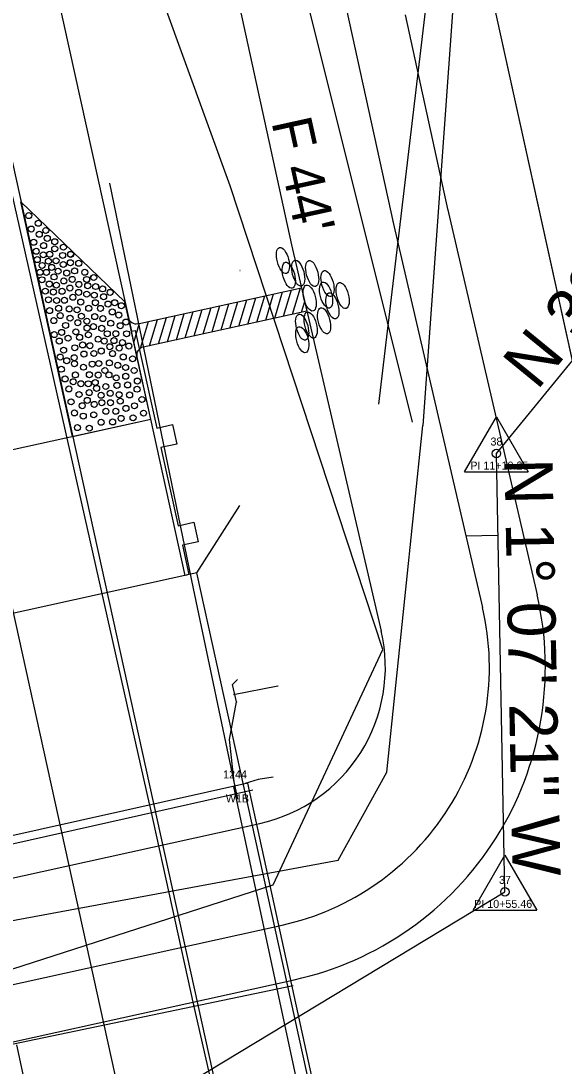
# Model space of a CAD drawing. Extents: x 2519952 to 2531965, y 848341 to 887632.
# Drawn here: x 2528431.4 to 2528499.3, y 851960.5 to 852091.1 of the extents above; entities that cross this region are included whole.
import ezdxf

# ---------------------------------------------------------------- set-up
doc = ezdxf.new("R2010")
doc.units = 0
for name, color, linetype in [('RD_EV_JW', 7, 'Continuous'), ('RD_EX_BldgApp', 7, 'Continuous'), ('RD_EX_BldgApp_txCode', 7, 'Continuous'), ('RD_EX_Bridge', 7, 'Continuous'), ('RD_EX_Conc', 7, 'Continuous'), ('RD_EX_DR_Pipe', 7, 'Continuous'), ('RD_EX_DV_Prop', 7, 'Continuous'), ('RD_EX_GuardRail', 7, 'Continuous'), ('RD_EX_H2O', 7, 'Continuous'), ('RD_EX_Misc', 7, 'Continuous'), ('RD_EX_Road', 7, 'Continuous'), ('RD_EX_RW', 7, 'Continuous'), ('RD_EX_VEG', 7, 'Continuous'), ('RD_HC_Cl', 7, 'Continuous'), ('RD_HC_Data', 7, 'Continuous'), ('RD_HC_Data_Tic', 7, 'Continuous'), ('RD_HC_txCode', 7, 'Continuous'), ('RD_PD_BCA', 7, 'Continuous'), ('RD_PD_Bridge', 7, 'Continuous'), ('RD_PD_CstnLmt', 7, 'Continuous'), ('RD_PD_DR_ErosCtrl', 7, 'Continuous'), ('RD_PD_Final_TrvlWay', 7, 'Continuous'), ('RD_PD_GR', 7, 'Continuous'), ('RD_PD_PaveShd', 7, 'Continuous'), ('RD_PD_TX_CstnLmt', 7, 'Continuous'), ('RD_SMD_Locator', 7, 'Continuous')]:
    doc.layers.add(name, color=color, linetype=linetype)

# ---------------------------------------------------------------- blocks, each defined once
blk = doc.blocks.new('TBC1')
at = {"layer": 'RD_PD_GR'}
blk.add_lwpolyline([(12.5, 2.5), (15, 2.5), (15, 0.49), (25, 0.49), (25, 2.5), (27.5, 2.5), (27.5, 0.49), (31.25, 0.49), (31.25, 0), (0, 0), (0, 0.49), (12.5, 0.49)], close=True, dxfattribs=at)

msp = doc.modelspace()

# ---------------------------------------------------------------- linework, layer by layer
at = {"layer": 'RD_EV_JW'}
msp.add_lwpolyline([(2528415.9, 851967.97), (2528462.94, 851983.14), (2528476.65, 852012.57), (2528457.58, 852070.48), (2528432.54, 852139.5), (2528402.93, 852278.26), (2528385.41, 852350.81), (2528363.37, 852451.24), (2528353.45, 852495.96), (2528382.56, 852499.75), (2528412.03, 852505.69)], dxfattribs=at)
at = {"layer": 'RD_EX_BldgApp'}
msp.add_lwpolyline([(2528474.17, 851921.38), (2528466.05, 851957.9), (2528458.04, 851995.44)], dxfattribs=at)
at = {"layer": 'RD_EX_Bridge'}
for points in [[(2528462.93, 851996.59), (2528461.07, 851996.29), (2528459.44, 851995.8)], [(2528429.64, 851911.53), (2528475.93, 851921.77), (2528459.8, 851995.83), (2528412.88, 851985.37), (2528429.64, 851911.53)]]:
    msp.add_lwpolyline(points, dxfattribs=at)
at = {"layer": 'RD_EX_Conc'}
msp.add_lwpolyline([(2528458.07, 851996.01), (2528457.47, 852001.29), (2528458.38, 852005.99), (2528457.85, 852008.18), (2528458.5, 852008.82)], dxfattribs=at)
at = {"layer": 'RD_EX_DR_Pipe'}
msp.add_line((2528458, 852006.91), (2528463.54, 852007.99), dxfattribs=at)
at = {"layer": 'RD_EX_DV_Prop'}
msp.add_line((2528484.88, 852118.66), (2528549.4, 851825.68), dxfattribs=at)
at = {"layer": 'RD_EX_GuardRail'}
msp.add_lwpolyline([(2528458.52, 851993.85), (2528452.97, 852020.19), (2528442.53, 852070.83)], dxfattribs=at)
at = {"layer": 'RD_EX_H2O'}
for points in [[(2528719.59, 851999.09), (2528691.1, 852047.72), (2528711.96, 852086.66), (2528686.69, 852125.57), (2528637.99, 852160.23), (2528595.34, 852145.76), (2528559.57, 852138.95), (2528529.72, 852106.03), (2528505.05, 852114.18), (2528485.4, 852092.73), (2528481.66, 852040.55)], [(2528393.64, 851981.43), (2528398.43, 851972.78), (2528471.09, 851986.23), (2528477.16, 851997.23), (2528481.66, 852040.55)]]:
    msp.add_lwpolyline(points, dxfattribs=at)
at = {"layer": 'RD_EX_Misc'}
for p, q in [((2528413.19, 851984.4), (2528460.39, 851995)), ((2528465.45, 851970.51), (2528418.56, 851960.74))]:
    msp.add_line(p, q, dxfattribs=at)
msp.add_lwpolyline([(2528721.04, 851999.29), (2528692.03, 852048.08), (2528712.68, 852087), (2528694.26, 852117.1), (2528687.66, 852126.5), (2528638.26, 852161.91), (2528594.97, 852147.21), (2528558.87, 852140.18), (2528529.59, 852106.6), (2528504.69, 852116.44), (2528482.38, 852095.87), (2528476.12, 852043.21)], dxfattribs=at)
at = {"layer": 'RD_EX_Road'}
for p, q in [((2528447.51, 851993.25), (2528425.97, 852088.72)), ((2528447.63, 851992.76), (2528447.51, 851993.25)), ((2528453.04, 851968.08), (2528447.63, 851992.76)), ((2528458.52, 851943.88), (2528453.04, 851968.08)), ((2528436.25, 851938.7), (2528430.91, 851963.15))]:
    msp.add_line(p, q, dxfattribs=at)
at = {"layer": 'RD_EX_RW'}
msp.add_line((2528484.89, 852118.66), (2528549.4, 851825.67), dxfattribs=at)
at = {"layer": 'RD_EX_VEG'}
msp.add_lwpolyline([(2528480.36, 852040.95), (2528466.6, 852096.04), (2528387.76, 852488.16), (2528341.84, 852710.17)], dxfattribs=at)
at = {"layer": 'RD_HC_Cl'}
for p, q in [((2528295.9, 852628.14), (2528852.49, 850100.49)), ((2528490.84, 852037.04), (2528538.4, 852095.17)), ((2528491.91, 851982.26), (2528490.84, 852037.04)), ((2528326.78, 851882.57), (2528491.91, 851982.26))]:
    msp.add_line(p, q, dxfattribs=at)
at = {"layer": 'RD_HC_Data'}
for p, q in [((2528486.87, 852034.74), (2528490.84, 852041.62)), ((2528490.84, 852041.62), (2528494.81, 852034.74)), ((2528486.87, 852034.74), (2528494.81, 852034.74)), ((2528487.94, 851979.97), (2528491.91, 851986.85)), ((2528491.91, 851986.85), (2528495.88, 851979.97)), ((2528487.94, 851979.97), (2528495.88, 851979.97))]:
    msp.add_line(p, q, dxfattribs=at)
for centre in [(2528490.84, 852037.04), (2528491.91, 851982.26)]:
    msp.add_circle(centre, 0.529, dxfattribs=at)
at = {"layer": 'RD_HC_Data_Tic'}
msp.add_line((2528491.04, 852026.78), (2528487.04, 852026.7), dxfattribs=at)
at = {"layer": 'RD_PD_BCA'}
for p, q in [((2528479.43, 852091.86), (2528484.78, 852067.41)), ((2528484.73, 852067.66), (2528495.93, 852019.39))]:
    msp.add_line(p, q, dxfattribs=at)
msp.add_lwpolyline([(2528416.79, 851960.53), (2528465.57, 851971.27)], dxfattribs=at)
msp.add_arc((2528456.97, 852010.34), 40, 282.4185, 13.0724, dxfattribs=at)
at = {"layer": 'RD_PD_Bridge'}
for p, q in [((2528404.67, 852031.88), (2528447.64, 852041.34)), ((2528451.94, 852021.81), (2528447.64, 852041.34)), ((2528453.41, 852022.13), (2528458.79, 852030.56))]:
    msp.add_line(p, q, dxfattribs=at)
for points in [[(2528453.41, 852022.13), (2528407.51, 852012.02)], [(2528481.36, 851895.17), (2528453.41, 852022.13)]]:
    msp.add_lwpolyline(points, dxfattribs=at)
at = {"layer": 'RD_PD_CstnLmt'}
for p, q in [((2528443.88, 852160.82), (2528465.24, 852063.13)), ((2528465.24, 852063.13), (2528476.45, 852014.86))]:
    msp.add_line(p, q, dxfattribs=at)
msp.add_lwpolyline([(2528412.49, 851980.06), (2528461.27, 851990.81)], dxfattribs=at)
msp.add_arc((2528456.97, 852010.34), 20, 282.4185, 13.0724, dxfattribs=at)
at = {"layer": 'RD_PD_DR_ErosCtrl'}
for p, q in [((2528456.58, 852163.6), (2528477.94, 852065.91)), ((2528477.91, 852066.07), (2528489.12, 852017.8))]:
    msp.add_line(p, q, dxfattribs=at)
msp.add_lwpolyline([(2528415.28, 851967.37), (2528464.07, 851978.11)], dxfattribs=at)
msp.add_arc((2528456.97, 852010.34), 33, 282.4185, 13.0724, dxfattribs=at)
at = {"layer": 'RD_PD_Final_TrvlWay'}
msp.add_line((2528396.48, 852227.18), (2528670.67, 850982.01), dxfattribs=at)
at = {"layer": 'RD_PD_GR'}
msp.add_line((2528396.83, 852272.06), (2528445.22, 852052.33), dxfattribs=at)
at = {"layer": 'RD_PD_PaveShd'}
for p, q in [((2528431.42, 852068.49), (2528444.41, 852055.99)), ((2528437.87, 852039.19), (2528431.42, 852068.49)), ((2528446.04, 852053.27), (2528466.49, 852057.77)), ((2528459.79, 852053.22), (2528460.77, 852056.51)), ((2528459.79, 852053.22), (2528460.77, 852056.51)), ((2528460.9, 852053.47), (2528461.89, 852056.75)), ((2528462.02, 852053.71), (2528463, 852057)), ((2528462.02, 852053.71), (2528463, 852057)), ((2528463.14, 852053.96), (2528464.12, 852057.25)), ((2528463.14, 852053.96), (2528464.12, 852057.25)), ((2528464.25, 852054.2), (2528465.24, 852057.49)), ((2528464.25, 852054.2), (2528465.12, 852057.09)), ((2528465.37, 852054.45), (2528466.36, 852057.74)), ((2528465.37, 852054.45), (2528466.36, 852057.74)), ((2528466.49, 852057.77), (2528467.17, 852054.84)), ((2528445.06, 852053.06), (2528444.41, 852055.99)), ((2528454.2, 852051.99), (2528455.18, 852055.28)), ((2528454.2, 852051.99), (2528455.18, 852055.28)), ((2528455.32, 852052.24), (2528456.3, 852055.53)), ((2528455.32, 852052.24), (2528456.3, 852055.53)), ((2528456.43, 852052.49), (2528457.42, 852055.77)), ((2528456.43, 852052.49), (2528457.42, 852055.77)), ((2528457.55, 852052.73), (2528458.54, 852056.02)), ((2528457.55, 852052.73), (2528458.54, 852056.02)), ((2528458.67, 852052.98), (2528459.65, 852056.26)), ((2528458.67, 852052.98), (2528459.65, 852056.26)), ((2528460.9, 852053.47), (2528461.77, 852056.35)), ((2528466.49, 852054.69), (2528466.89, 852056.04)), ((2528466.49, 852054.69), (2528466.89, 852056.04)), ((2528467.17, 852054.84), (2528446.68, 852050.34)), ((2528448.61, 852050.77), (2528449.6, 852054.05)), ((2528448.61, 852050.77), (2528449.6, 852054.05)), ((2528449.73, 852051.01), (2528450.71, 852054.3)), ((2528449.73, 852051.01), (2528450.71, 852054.3)), ((2528450.85, 852051.26), (2528451.83, 852054.55)), ((2528451.96, 852051.5), (2528452.95, 852054.79)), ((2528451.96, 852051.5), (2528452.95, 852054.79)), ((2528453.08, 852051.75), (2528454.07, 852055.04)), ((2528453.08, 852051.75), (2528454.07, 852055.04)), ((2528445.71, 852050.13), (2528445.06, 852053.06)), ((2528445.53, 852050.93), (2528446.24, 852053.32)), ((2528446.36, 852050.21), (2528447.36, 852053.56)), ((2528447.5, 852050.52), (2528448.48, 852053.81)), ((2528447.5, 852050.52), (2528448.48, 852053.81)), ((2528447.64, 852041.34), (2528445.71, 852050.13)), ((2528437.87, 852039.19), (2528447.64, 852041.34))]:
    msp.add_line(p, q, dxfattribs=at)
for centre in [(2528432.4, 852066.78), (2528433.59, 852065.82), (2528433.59, 852065.82), (2528432.7, 852065.1), (2528432.7, 852065.1), (2528433.71, 852064.45), (2528433.71, 852064.45), (2528434.53, 852064.92), (2528434.53, 852064.92), (2528433.02, 852063.44), (2528433.02, 852063.44), (2528434.26, 852063.03), (2528434.26, 852063.03), (2528434.71, 852063.93), (2528434.71, 852063.93), (2528435.64, 852063.51), (2528436.73, 852062.83), (2528436.73, 852062.83), (2528433.33, 852062.32), (2528433.33, 852062.32), (2528434.21, 852061.88), (2528434.21, 852061.88), (2528435.02, 852061.95), (2528435.02, 852061.95), (2528435.64, 852062.63), (2528435.64, 852062.63), (2528436.63, 852061.8), (2528436.63, 852061.8), (2528437.61, 852061.96), (2528437.64, 852061.93), (2528433.47, 852061.28), (2528433.47, 852061.28), (2528434.07, 852060.55), (2528434.07, 852060.55), (2528434.85, 852061.08), (2528434.85, 852061.08), (2528435.27, 852060.31), (2528435.27, 852060.31), (2528435.81, 852061.13), (2528435.81, 852061.13), (2528436.71, 852060.67), (2528436.71, 852060.67), (2528437.6, 852060.89), (2528437.6, 852060.89), (2528438.64, 852060.82), (2528438.64, 852060.82), (2528433.81, 852059.7), (2528433.81, 852059.7), (2528434.05, 852058.76), (2528434.05, 852058.76), (2528434.61, 852059.68), (2528434.61, 852059.68), (2528435.56, 852059.12), (2528435.56, 852059.12), (2528436.07, 852059.83), (2528436.07, 852059.83), (2528437.14, 852059.6), (2528437.14, 852059.6), (2528437.83, 852058.81), (2528437.83, 852058.81), (2528438.13, 852059.87), (2528438.13, 852059.87), (2528439.4, 852059.7), (2528439.4, 852059.7), (2528439.63, 852058.8), (2528439.63, 852058.8), (2528440.52, 852059.04), (2528440.53, 852059.04), (2528434.97, 852058.23), (2528434.97, 852058.23), (2528435.85, 852058.09), (2528435.85, 852058.09), (2528436.78, 852058.61), (2528436.78, 852058.61), (2528437.54, 852057.73), (2528437.54, 852057.73), (2528438.66, 852058.18), (2528438.66, 852058.18), (2528439.77, 852058.02), (2528439.77, 852058.02), (2528440.75, 852057.91), (2528440.75, 852057.91), (2528441.63, 852057.62), (2528441.63, 852057.62), (2528434.46, 852057.34), (2528434.46, 852057.34), (2528434.86, 852056.26), (2528434.86, 852056.26), (2528435.48, 852057.23), (2528435.48, 852057.23), (2528435.88, 852056.17), (2528435.88, 852056.17), (2528436.56, 852057.32), (2528436.56, 852057.32), (2528436.86, 852056.19), (2528436.86, 852056.19), (2528437.91, 852056.57), (2528437.91, 852056.57), (2528438.63, 852057.18), (2528438.63, 852057.18), (2528439.64, 852056.96), (2528439.64, 852056.96), (2528440.59, 852056.84), (2528440.59, 852056.84), (2528441.75, 852056.64), (2528441.75, 852056.64), (2528442.57, 852057.18), (2528442.57, 852057.18), (2528435.01, 852054.91), (2528435.01, 852054.91), (2528436.13, 852055.2), (2528436.13, 852055.2), (2528437.45, 852055.11), (2528437.45, 852055.11), (2528438.43, 852055), (2528438.43, 852055), (2528438.89, 852055.98), (2528438.89, 852055.98), (2528439.89, 852055.19), (2528439.89, 852055.19), (2528440.72, 852055.89), (2528440.72, 852055.89), (2528441.36, 852055.18), (2528441.36, 852055.18), (2528442.31, 852055.73), (2528442.31, 852055.73), (2528443.14, 852055.89), (2528443.14, 852055.89), (2528443.98, 852055.52), (2528443.98, 852055.52), (2528443.98, 852055.52), (2528435.53, 852053.66), (2528435.53, 852053.66), (2528436.33, 852054.28), (2528436.33, 852054.28), (2528437.56, 852053.96), (2528437.56, 852053.96), (2528438.98, 852054.21), (2528438.98, 852054.21), (2528439.66, 852053.59), (2528439.66, 852053.59), (2528440.64, 852054.16), (2528440.64, 852054.16), (2528441.66, 852053.91), (2528441.66, 852053.91), (2528442.84, 852054.74), (2528442.84, 852054.74), (2528443.65, 852054.35), (2528443.65, 852054.35), (2528436.51, 852052.19), (2528436.51, 852052.19), (2528437, 852053.05), (2528437, 852053.05), (2528438.29, 852052.25), (2528438.29, 852052.25), (2528438.53, 852053.39), (2528438.53, 852053.39), (2528439.69, 852052.72), (2528439.69, 852052.72), (2528440.49, 852052.9), (2528440.49, 852052.9), (2528441.52, 852052.69), (2528441.52, 852052.69), (2528442.64, 852053.33), (2528442.64, 852053.33), (2528443.83, 852053.02), (2528443.83, 852053.02), (2528444.55, 852053.48), (2528444.55, 852053.48), (2528435.58, 852051.91), (2528435.58, 852051.91), (2528436.21, 852051.1), (2528436.21, 852051.1), (2528437.31, 852051.46), (2528437.31, 852051.46), (2528438.75, 852051.57), (2528438.75, 852051.57), (2528439.85, 852051.88), (2528439.85, 852051.88), (2528441.07, 852051.33), (2528441.07, 852051.33), (2528441.83, 852051.1), (2528441.83, 852051.1), (2528442.21, 852052.01), (2528442.21, 852052.01), (2528443.05, 852051.15), (2528443.05, 852051.15), (2528443.28, 852052.02), (2528443.28, 852052.02), (2528444.11, 852050.9), (2528444.11, 852050.9), (2528444.63, 852052.01), (2528444.63, 852052.01), (2528436.75, 852049.96), (2528436.75, 852049.96), (2528438.15, 852050.26), (2528438.15, 852050.26), (2528439.13, 852050.61), (2528439.13, 852050.61), (2528440.04, 852050.52), (2528440.04, 852050.52), (2528441.46, 852049.85), (2528441.46, 852049.85), (2528442.53, 852050.39), (2528442.53, 852050.39), (2528443.7, 852050.23), (2528443.7, 852050.23), (2528444.91, 852050.47), (2528444.91, 852050.47), (2528436.33, 852049.1), (2528437.14, 852048.64), (2528437.14, 852048.64), (2528438.08, 852049.02), (2528438.08, 852049.02), (2528438.11, 852048.27), (2528438.11, 852048.27), (2528439.3, 852049.48), (2528439.3, 852049.48), (2528440.54, 852049.55), (2528440.54, 852049.55), (2528441.15, 852048.29), (2528441.15, 852048.29), (2528442.48, 852048.37), (2528442.48, 852048.37), (2528442.87, 852049.53), (2528442.87, 852049.53), (2528444.21, 852049.11), (2528444.21, 852049.11), (2528445.38, 852048.88), (2528445.38, 852048.88), (2528436.47, 852047.58), (2528436.47, 852047.58), (2528439.24, 852047.83), (2528439.24, 852047.83), (2528440.33, 852048.22), (2528440.33, 852048.22), (2528441.91, 852047.42), (2528441.91, 852047.42), (2528443.53, 852048.07), (2528443.53, 852048.07), (2528444.5, 852047.8), (2528444.5, 852047.8), (2528445.57, 852047.42), (2528445.57, 852047.42), (2528436.94, 852046.36), (2528436.94, 852046.36), (2528437.95, 852046.02), (2528437.95, 852046.02), (2528438.23, 852046.87), (2528438.23, 852046.87), (2528438.91, 852045.77), (2528438.91, 852045.77), (2528439.84, 852045.76), (2528439.84, 852045.76), (2528439.97, 852046.89), (2528439.97, 852046.89), (2528440.71, 852045.92), (2528440.71, 852045.92), (2528441.08, 852046.85), (2528441.08, 852046.85), (2528442.42, 852046.87), (2528442.42, 852046.87), (2528443.33, 852046.5), (2528443.33, 852046.5), (2528444.52, 852046.7), (2528444.52, 852046.7), (2528445.98, 852046.1), (2528445.98, 852046.1), (2528437.41, 852045.11), (2528437.41, 852045.11), (2528438.68, 852044.42), (2528438.68, 852044.42), (2528439.95, 852044.66), (2528439.95, 852044.66), (2528440.88, 852045.18), (2528442.03, 852045.42), (2528442.03, 852045.42), (2528442.58, 852044.57), (2528442.58, 852044.57), (2528443.42, 852045.56), (2528443.42, 852045.56), (2528443.69, 852044.39), (2528443.69, 852044.39), (2528444.76, 852045.62), (2528444.76, 852045.62), (2528445.01, 852044.37), (2528445.01, 852044.37), (2528445.93, 852045.08), (2528445.93, 852045.08), (2528437.68, 852043.5), (2528437.68, 852043.5), (2528439.71, 852043.69), (2528439.71, 852043.69), (2528440.58, 852043.19), (2528440.58, 852043.19), (2528441.44, 852044.32), (2528441.44, 852044.32), (2528441.53, 852043.39), (2528441.53, 852043.39), (2528442.61, 852043.39), (2528442.61, 852043.39), (2528443.84, 852043.59), (2528443.84, 852043.59), (2528446.55, 852043.8), (2528446.55, 852043.8), (2528438.11, 852042.11), (2528438.11, 852042.11), (2528439.08, 852043.02), (2528439.08, 852043.02), (2528440.52, 852041.88), (2528440.52, 852041.88), (2528442.04, 852042.32), (2528442.04, 852042.32), (2528443.28, 852042.32), (2528443.28, 852042.32), (2528444.55, 852042.68), (2528444.55, 852042.68), (2528445.61, 852043.01), (2528445.61, 852043.01), (2528446.74, 852042.09), (2528446.74, 852042.09), (2528446.74, 852042.09), (2528439.21, 852041.72), (2528439.21, 852041.72), (2528441.44, 852040.95), (2528441.44, 852040.95), (2528442.88, 852040.99), (2528442.88, 852040.99), (2528443.94, 852041.44), (2528443.94, 852041.44), (2528445.43, 852041.51), (2528445.43, 852041.51), (2528438.49, 852040.28), (2528438.49, 852040.28), (2528439.96, 852040.21), (2528439.96, 852040.21)]:
    msp.add_circle(centre, 0.375, dxfattribs=at)
for centre, start, end in [((2528445.82, 852054.25), 192.4185, 282.3889), ((2528446.9, 852049.37), 102.3889, 192.4185)]:
    msp.add_arc(centre, 1, start, end, dxfattribs=at)
for centre in [(2528464.17, 852061.17), (2528464.9, 852059.32), (2528466.07, 852059.59), (2528466.07, 852059.59), (2528467.82, 852059.54), (2528467.82, 852059.54), (2528469.74, 852058.28), (2528469.74, 852058.28), (2528467.51, 852056.48), (2528467.51, 852056.48), (2528469.56, 852056.85), (2528469.56, 852056.85), (2528471.63, 852056.79), (2528471.63, 852056.79), (2528470.35, 852055.5), (2528470.35, 852055.5), (2528469.31, 852053.63), (2528469.31, 852053.63), (2528466.57, 852052.84), (2528466.57, 852052.84), (2528467.63, 852053.1), (2528467.63, 852053.1), (2528466.58, 852051.27), (2528466.58, 852051.27)]:
    msp.add_ellipse(centre, major_axis=(-0.43, 1.62), ratio=0.429445, dxfattribs=at)
at = {"layer": 'RD_SMD_Locator'}
for centre in [(2528442.53, 852070.83), (2528457.58, 852070.48), (2528458.8, 852059.9), (2528476.12, 852043.21), (2528480.36, 852040.95), (2528481.66, 852040.55), (2528481.66, 852040.55), (2528490.84, 852037.04), (2528452.97, 852020.19), (2528476.65, 852012.57), (2528457.85, 852008.18), (2528458.5, 852008.82), (2528458, 852006.91), (2528463.54, 852007.99), (2528458.38, 852005.99), (2528457.47, 852001.29), (2528462.93, 851996.59), (2528477.16, 851997.23), (2528458.04, 851995.44), (2528458.07, 851996.01), (2528459.44, 851995.8), (2528459.8, 851995.83), (2528461.07, 851996.29), (2528458.52, 851993.85), (2528460.39, 851995), (2528447.51, 851993.25), (2528447.63, 851992.76), (2528471.09, 851986.23), (2528462.94, 851983.14), (2528491.91, 851982.26), (2528465.45, 851970.51), (2528453.04, 851968.08)]:
    msp.add_circle(centre, 0.001, dxfattribs=at)

# ---------------------------------------------------------------- block references
at = {"layer": 'RD_PD_Bridge', "rotation": -77.58151740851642}
msp.add_blockref('TBC1', (2528445.22, 852052.33), dxfattribs=at)

# ---------------------------------------------------------------- texts
at = {"layer": 'RD_EX_BldgApp_txCode'}
for s, p in [('1244', (2528456.69, 851996.44)), ('W1B', (2528457.03, 851993.44))]:
    msp.add_text(s, height=1, dxfattribs=at).set_placement(p)
at = {"layer": 'RD_HC_Data'}
for s, rotation, p in [('N 39%%d 17\' 08" E', 50.7144, (2528495.93, 852044.84)), ('N 1%%d 07\' 21" W', 271.1226, (2528491.85, 852036.38))]:
    msp.add_text(s, height=6, rotation=rotation, dxfattribs=at).set_placement(p)
at = {"layer": 'RD_HC_txCode'}
for s, p in [('38', (2528490.11, 852038.04)), ('PI 11+10.25', (2528487.59, 852035.04)), ('37', (2528491.18, 851983.26)), ('PI 10+55.46', (2528488.07, 851980.26))]:
    msp.add_text(s, height=1, dxfattribs=at).set_placement(p)
at = {"layer": 'RD_PD_TX_CstnLmt'}
msp.add_text("F 44'", height=5, rotation=282.4185, dxfattribs=at).set_placement((2528462.71, 852078.49))

doc.saveas('drawing.dxf')
